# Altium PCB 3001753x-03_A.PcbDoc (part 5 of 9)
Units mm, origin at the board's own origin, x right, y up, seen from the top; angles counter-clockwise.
Board outline 210 x 130 mm, 8 copper layers (1-TOP, 2-GND, 3-INTOP, 4-PWR, 5-PWR, 6-INBOT, 7-GND, 8-BOTTOM), stack 1.646 mm thick; 676 components, 623 nets, 2861 pads, 2382 vias.
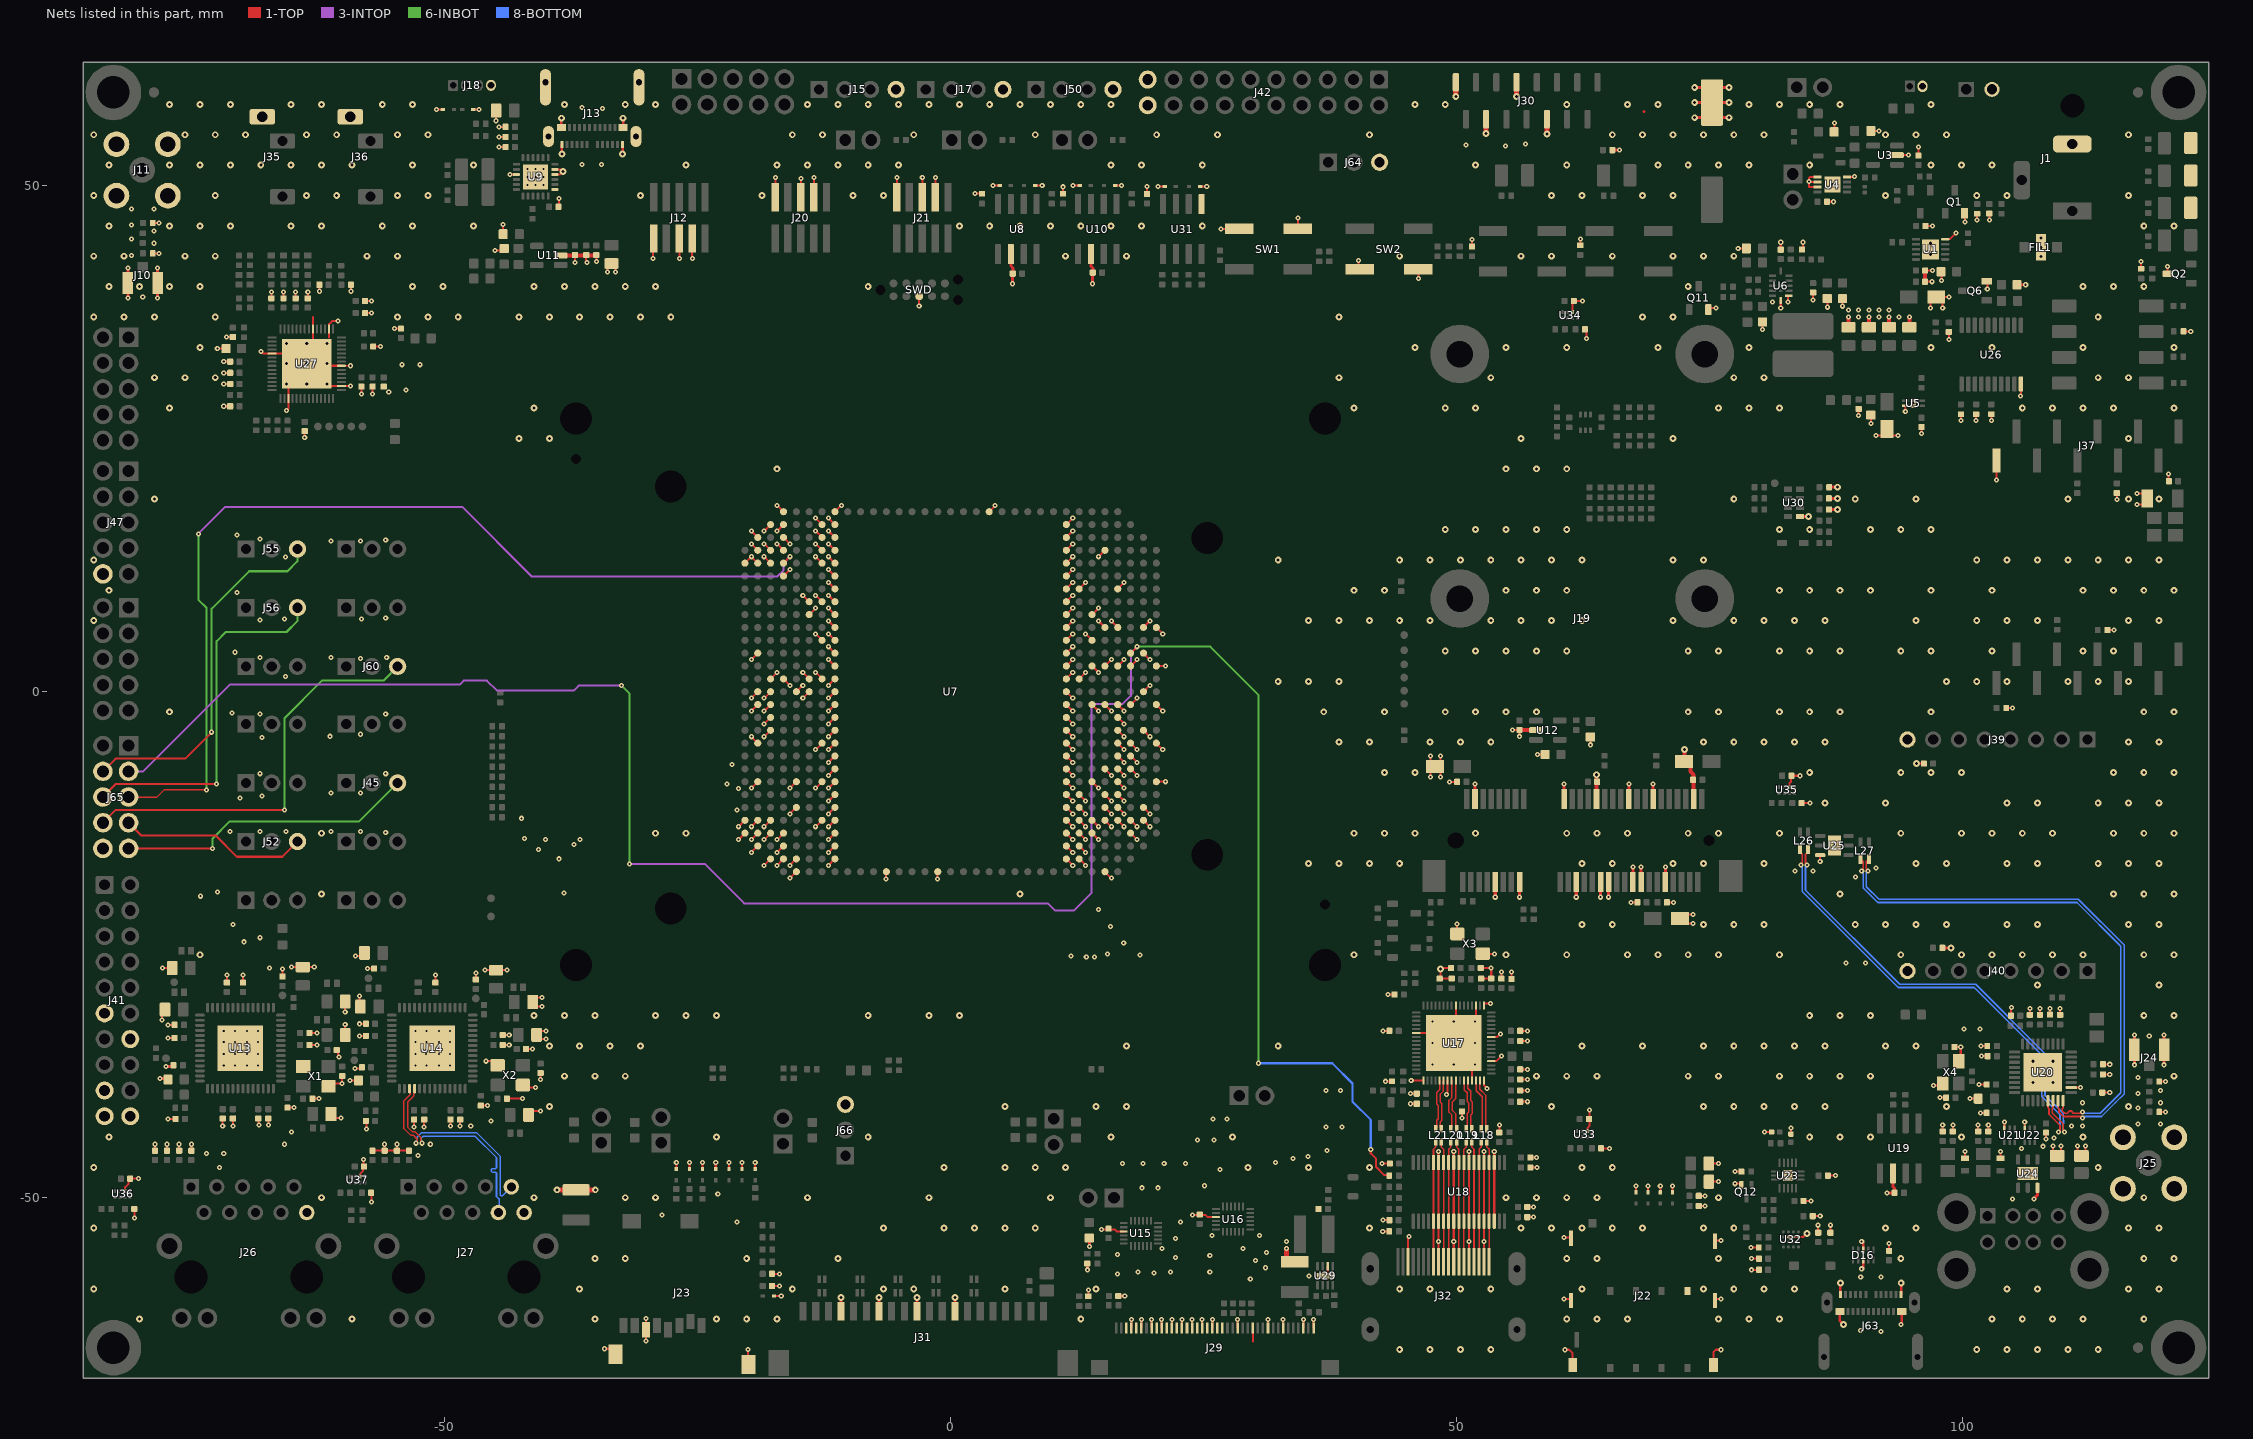
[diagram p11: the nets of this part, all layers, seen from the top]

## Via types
v1: diameter 0.5, hole 0.2, 1-TOP to 8-BOTTOM, 1547 vias
v2: diameter 0.68, hole 0.3, 1-TOP to 8-BOTTOM, 835 vias

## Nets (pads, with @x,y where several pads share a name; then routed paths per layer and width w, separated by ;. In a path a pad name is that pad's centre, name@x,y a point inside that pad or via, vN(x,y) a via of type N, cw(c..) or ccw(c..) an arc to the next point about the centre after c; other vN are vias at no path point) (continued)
ETH2_TXRXD_N: J27.9 U14.17 | length 21.8
  1-TOP w0.15: U14.17@-53.45,-39.2 -53.377,-39.273 -53.377,-39.777 -54,-40.4 -54,-43.147 -53.347,-43.8 -53.077,-43.8 -52.677,-44.2 -52.677,-44.477 v1(-52.8,-44.6)
  8-BOTTOM w0.15: v1(-52.8,-44.6) -52.677,-44.477 -52.677,-43.976 -52.247,-43.546 -46.829,-43.546 -44.504,-45.871 -44.504,-49.714 -44.416,-49.802 -44.292,-49.802 J27.9@-43.4,-48.91
ETH2_TXRXD_P: J27.8 U14.18 | length 21.7
  1-TOP w0.15: U14.18@-52.95,-39.2 -53.023,-39.273 -53.023,-39.924 -53.646,-40.547 -53.646,-43 -53.2,-43.446 -52.93,-43.446 -52.323,-44.053 -52.323,-44.477 v1(-52.2,-44.6)
  8-BOTTOM w0.15: v1(-52.2,-44.6) -52.323,-44.477 -52.323,-44.123 -52.1,-43.9 -46.976,-43.9 -44.858,-46.018 -44.858,-46.588 -44.858,-47.013 -44.946,-47.101 -45.294,-47.101 -45.364,-47.171 -45.364,-47.381 -45.294,-47.451 -44.946,-47.451 -44.858,-47.539 -44.858,-47.713 -44.858,-49.861 -44.581,-50.138 J27.8@-44.581,-51.361
FAA_N: L27.1 U20.8 | length 54.3
  1-TOP w0.168: v1(90.6,-17.7) 90.459,-17.559 90.459,-16.791 L27.1@90.7,-16.55 ; U20.8@109.4,-40.4 109.4,-41.1 109.491,-41.191 109.491,-41.541 109.775,-41.825 109.909,-41.959 111.659,-41.959 v1(111.8,-42.1)
  8-BOTTOM w0.168: v1(90.6,-17.7) 90.459,-17.841 90.459,-19.259 91.7,-20.5 111.4,-20.5 115.918,-25.018 115.918,-39.732 115.073,-40.576 113.691,-41.959 111.941,-41.959 v1(111.8,-42.1)
FAA_P: L27.4 U20.9 | length 53.5
  1-TOP w0.168: L27.4@89.9,-16.55 90.141,-16.791 90.141,-17.559 v1(90,-17.7) ; U20.9@109.9,-40.4 109.9,-41.1 109.809,-41.191 109.809,-41.409 110.041,-41.641 110.333,-41.641 110.432,-41.543 110.432,-41.483 110.505,-41.41 110.726,-41.41 110.8,-41.483 110.8,-41.543 110.898,-41.641 111.659,-41.641 v1(111.8,-41.5)
  8-BOTTOM w0.168: v1(90,-17.7) 90.141,-17.841 90.141,-19.391 91.568,-20.818 111.268,-20.818 115.6,-25.15 115.6,-39.6 113.559,-41.641 111.941,-41.641 v1(111.8,-41.5)
G_N: L26.4 U20.6 | length 46.5
  1-TOP w0.168: L26.4@83.892,-15.84 84.008,-15.956 84.035,-15.956 84.133,-16.054 84.133,-16.467 84.133,-16.959 v1(83.992,-17.1) ; U20.6@108.4,-40.4 108.4,-41.1 108.491,-41.191 108.491,-41.741 109.582,-42.832 109.582,-43.359 v1(109.441,-43.5)
  8-BOTTOM w0.168: v1(83.992,-17.1) 84.133,-17.241 84.133,-18.202 84.133,-18.333 84.133,-19.733 93.618,-29.218 101.118,-29.218 107.782,-35.882 107.782,-39.982 109.582,-41.782 109.582,-43.359 v1(109.441,-43.5)
G_P: L26.1 U20.7 | length 46.6
  1-TOP w0.168: v1(84.592,-17.1) 84.451,-16.959 84.451,-16.9 84.451,-16.054 84.55,-15.956 84.576,-15.956 L26.1@84.692,-15.84 ; U20.7@108.9,-40.4 108.9,-41.1 108.809,-41.191 108.809,-41.609 109.9,-42.7 109.9,-43.359 v1(110.041,-43.5)
  8-BOTTOM w0.168: v1(84.592,-17.1) 84.451,-17.241 84.451,-19.602 93.75,-28.9 101.25,-28.9 108.1,-35.75 108.1,-39.85 109.9,-41.65 109.9,-42.325 109.925,-42.35 109.925,-42.675 109.9,-42.7 109.9,-43.359 v1(110.041,-43.5)
GND: C1.1 C2.2 C3.1 C4.1 C5.1 C6.2 C7.1 C8.1 C9.2 C10.2 C12.1 C13.1 C14.1 C15.1 C16.2 C17.1 C18.1 C19.1 C20.1 C21.1 C22.1 C24.1 C25.1 C26.1 C27.1 C28.1 C29.2 C30.1 C31.2 C32.2 C33.1 C34.2 C35.1 C36.1 C37.1 C38.1 C39.2 C40.2 C41.2 C42.2 C43.1 C44.1 C45.1 C46.1 C47.1 C48.1 C49.1 C50.1 C51.1 C52.1 C53.1 C54.1 C55.1 C56.1 C57.1 C58.1 C59.1 C60.1 C61.1 C62.1 C63.1 C64.1 C65.1 C66.1 C67.2 C68.1 C69.1 C70.1 C71.1 C72.1 C73.1 C74.1 C75.1 C76.1 C77.1 C78.1 C79.1 C81.1 C82.1 C83.1 C84.1 C85.1 C86.1 C87.1 C88.1 C89.1 C90.1 C91.1 C92.1 C93.1 C94.2 C95.1 C96.1 C97.1 C98.1 C99.1 C100.1 C101.1 C102.1 C103.1 C104.1 C105.1 C106.1 C108.2 C109.2 C110.1 C111.1 C112.1 C113.1 C114.1 C115.1 C116.1 C118.1 C119.1 C120.1 C121.1 C122.1 C123.1 C124.1 C125.1 C126.1 C127.1 C128.1 C129.1 C130.1 C131.1 C132.1 C133.1 C134.1 C135.1 C136.1 C137.2 C138.2 C139.2 C140.1 C141.1 C142.1 C143.1 C144.1 C145.1 C146.2 C147.1 C148.1 C149.1 C150.1 C151.1 C152.1 C153.1 C154.1 C155.1 C156.1 C157.1 C158.2 C161.2 C164.2 C165.2 C166.2 C168.2 C170.2 C171.1 C173.1 C174.1 C175.1 C176.2 C177.2 C178.2 C179.1 C180.1 C181.1 C182.1 C183.2 C184.2 C185.1 C186.1 C187.1 C188.1 C189.1 C190.1 C191.1 C192.1 C193.1 C194.1 C195.1 C196.1 C197.1 C198.1 C199.1 C200.1 C201.1 C202.1 C203.2 C204.1 C205.2 C206.1 C207.2 C208.1 C209.2 C210.1 C211.2 D1.2 D3.1 D4.1 D7.1 D8.1 D9.1 D10.1 D11.1 D12.1 D13.1 D14.1 D16.3 D16.8 D19.1 D20.1 D22.A D23.A D24.2 D25.2 D26.2 D27.2 D28.2 D29.2 D30.2 D32.K D33.K D34.K FIL1.2 J1.2 J2.2 J4.2 J10.2 J10.3 J11.2 J11.3 J11.4 J11.5 J12.4 J12.6 J12.10 J13.A1 J13.A12 J13.B1 J13.B12 J13.MT1 J13.MT2 J13.MT3 J13.MT4 J15.4 J17.4 J18.4 J19.4 J19.9 J19.15 J19.18 J19.21 J19.26 J19.27 J19.29 J19.34 J19.35 J19.37 J19.40 J19.43 J19.50 J20.3 J20.5 J20.9 J21.3 J21.5 J21.9 J22.5 J22.11 J22.12 J22.13 J22.14 J22.15 J22.16 J23.6 J23.11 J23.12 J24.2 J24.3 J25.2 J25.3 J25.4 J25.5 J26.10 J27.10 J29.3 J29.4 J29.5 J29.6 J29.8 J29.9 J29.10 J29.11 J29.12 J29.13 J29.14 J29.15 J29.16 J29.17 J29.18 J29.19 J29.20 J29.21 J29.22 J29.25 J29.28 J29.31 J29.34 J29.38 J29.40 J30.6 J30.9 J30.12 J30.15 J31.4 J31.7 J31.10 J31.13 J32.2 J32.5 J32.8 J32.11 J32.17 J35.1 J36.1 J37.10 J39.8 J40.8 J41.11 J41.14 J41.17 J41.19 J41.20 J42.19 J42.20 J47.10 J50.4 J63.A1 J63.A12 J63.B1 J63.B12 J64.3 J65.10 J66.3 L24.1 L25.1 Q1.S Q2.D Q6.S Q11.S Q12.S R11.2 R14.2 R21.1 R31.1 R32.1 R59.1 R60.1 R67.1 R78.1 R79.1 R83.1 R95.1 R96.1 R100.1 R102.1 R106.1 R111.1 R114.1 R116.1 R117.2 R124.2 R125.1 R126.1 R144.2 R145.1 R146.1 R147.1 R148.1 R150.1 R157.1 R158.1 R159.1 R194.1 R198.1 R200.2 R202.1 R204.2 R208.1 R209.1 R218.2 R229.1 SW1.1 SW1.2 SW2.1 SW2.2 SWD.3 U1.5 U1.11 U3.2 U4.4 U4.5 U4.6 U4.7 U4.9 U5.2 U5.5 U6.1 U6.12 U7.A4 U7.A5 U7.A25 U7.AF2 U7.AF3 U7.AF4 U7.AF5 U7.AF6 U7.AF7 U7.AF8 U7.AF9 U7.AF10 U7.AF11 U7.AF12 U7.AF13 U7.AF14 U7.AF15 U7.AF16 U7.AF17 U7.AF18 U7.AF19 U7.AF20 U7.AF21 U7.AF22 U7.AF23 U7.AF24 U7.AF25 U7.AF26 U7.AF27 U7.AF28 U7.AG2 U7.AG3 U7.AG4 U7.AG5 U7.AG6 U7.AG7 U7.AG16 U7.AG23 U7.AH4 U7.AH5 U7.AH8 U7.AH14 U7.AH17 U7.AH19 U7.AH21 U7.AJ1 U7.AJ5 U7.AJ6 U7.AJ7 U7.AJ9 U7.AJ14 U7.AJ17 U7.AJ20 U7.AJ26 U7.AK5 U7.AK6 U7.AK7 U7.AK8 U7.AK9 U7.AK10 U7.AK11 U7.AK12 U7.AK13 U7.AK14 U7.AK17 U7.AK20 U7.AK23 U7.AL4 U7.AL5 U7.AL9 U7.AL10 U7.AL11 U7.AL14 U7.AL17 U7.AM5 U7.AM6 U7.AM12 U7.AM15 U7.AM18 U7.AM20 U7.AN8 U7.AN11 U7.AN14 U7.AN17 U7.AN20 U7.B3 U7.B4 U7.B5 U7.B8 U7.B11 U7.B14 U7.B15 U7.B18 U7.B25 U7.B26 U7.B27 U7.C2 U7.C4 U7.C5 U7.C12 U7.C13 U7.C14 U7.C15 U7.C16 U7.C25 U7.C26 U7.C28 U7.D2 U7.D3 U7.D4 U7.D16 U7.D24 U7.D26 U7.D27 U7.D28 U7.D29 U7.E1 U7.E2 U7.E6 U7.E8 U7.E15 U7.F15 U7.F16 U7.F21 U7.F22 U7.G5 U7.G8 U7.G11 U7.G16 U7.G19 U7.G22 U7.G25 U7.G26 U7.G27 U7.G28 U7.H2 U7.H3 U7.H4 U7.H5 U7.H6 U7.H7 U7.H8 U7.H9 U7.H10 U7.H11 U7.H12 U7.H13 U7.H14 U7.H15 U7.H16 U7.H17 U7.H18 U7.H19 U7.H20 U7.H21 U7.H22 U7.H23 U7.H24 U7.H25 U7.H26 U7.H27 U7.H28 U7.H29 U7.M1 U7.T1 U7.Y29 U8.2 U9.3 U9.13 U9.16 U9.17 U9.25 U10.2 U11.2 U12.2 U13.57 U14.57 U15.9 U16.9 U17.6 U17.17 U17.23 U17.29 U17.32 U17.36 U17.42 U17.49 U17.51 U17.56 U17.65 U18.3 U18.5 U18.8 U18.11 U18.14 U18.25 U18.28 U18.31 U18.34 U18.36 U19.6 U20.11 U20.37 U21.3 U22.3 U23.17 U24.3 U24.7 U25.3 U25.7 U26.10 U27.3 U27.16 U27.21 U27.30 U27.34 U27.47 U27.57 U29.2 U29.9 U30.5 U31.5 U32.B3 U32.C3 U32.D3 U33.2 U34.2 U35.2 U36.2 U37.2 X1.2 X1.4 X2.2 X2.4 X3.2 X3.4 X4.2 X4.4 | length 613.4
  1-TOP w0.15: U27.16@-60.17,30.2 v1(-59.3,30.2) ; U27.21@-60.17,32.2 v1(-59.3,32.2)
  1-TOP w0.168: U21.3@104.1,-43.15 v1(104.1,-42.5) ; U22.3@106.1,-43.15 v1(106.1,-42.5)
  1-TOP w0.2: U36.2@-81.55,-49.3 -81.549,-49.299 -81.549,-48.949 -81.2,-48.6 C208.1@-81.2,-48.3 ; C208.1@-81.04,-48.1 v1(-80.2,-48.1) ; C209.2@-80.64,-51.1 -80.6,-51.14 v1(-80.6,-52) ; R59.1@-78.82,43.3 v1(-78.2,43.3) ; R60.1@-78.82,46.3 v1(-78.2,46.3) ; C57.1@-78.6,-45.34 v1(-78.6,-44.7) ; v1(-77.9,-32.44) C76.1@-77.9,-31.8 ; v1(-77.84,-27.3) C66.1@-77.2,-27.3 ; C56.1@-77.4,-45.34 v1(-77.4,-44.7) ; v1(-77.3,-42.2) C67.2@-76.56,-42.2 ; v1(-77.3,-34.2) C77.1@-76.66,-34.2 ; v1(-77.3,-32.9) C72.1@-76.66,-32.9 ; C55.1@-76.2,-45.34 v1(-76.2,-44.7) ; C54.1@-75,-45.34 v1(-75,-44.7) ; v1(-72.44,33.9) C180.1@-71.8,33.9 ; v1(-71.9,-42.9) C73.1@-71.9,-42.26 ; v1(-71.8,28.2) C173.1@-71.16,28.2 ; v1(-71.8,30.4) C178.2@-71.16,30.4 ; v1(-71.8,31.5) C177.2@-71.16,31.5 ; v1(-71.8,32.6) C181.1@-71.16,32.6 ; v1(-71.54,35.04) C158.2@-70.9,35.04 ; C65.1@-71.5,-28.74 v1(-71.5,-28) ; U13.57@-71.4,-36.45 U13.57@-70.15,-35.2 ; v1(-70.9,-42.9) C61.1@-70.9,-42.26 ; C64.1@-69.9,-28.74 v1(-69.9,-28) ; C60.1@-68.4,-42.26 -68.35,-42.31 -68.35,-42.75 v1(-68.3,-42.8) ; v1(-68.1,33.6) -67.9,33.4 U27.47@-67.03,33.4 -66.1,33.4 ; v1(-67.4,-42.8) C74.1@-67.4,-42.26 ; C161.2@-67.1,38.86 v1(-67.1,39.5) ; C78.1@-66,-28.14 v1(-66,-27.4) ; C165.2@-65.9,38.86 v1(-65.9,39.5) ; v1(-65.6,27.8) -65.4,28 U27.3@-65.4,28.97 -65.4,29.9 ; R106.1@-65.5,-41.08 v1(-64.86,-41.08) ; v1(-65.1,-27.2) -64.3,-27.2 C79.1@-64,-26.9 ; C166.2@-64.7,38.86 v1(-64.7,39.5) ; v1(-63.8,25.1) C171.1@-63.8,25.74 ; C79.1@-63.6,-27.2 v1(-62.86,-27.2) ; v2(-63.6,32.4) -61.4,30.2 U27.16@-60.17,30.2 ; C170.2@-63.5,38.86 v1(-63.5,39.5) ; C58.1@-63.34,-34.9 v1(-62.6,-34.9) ; C75.1@-63.34,-33.7 v1(-62.6,-33.7) ; C71.1@-63.04,-40.2 v1(-62.4,-40.2) ; -63,34.9 U27.34@-63,35.83 -63,37 ; v1(-62.36,39.56) C164.2@-62.36,40.2 ; X1.4@-61.45,-38.975 -61.175,-38.7 v1(-60.1,-38.7) C68.1@-60.1,-37.96 ; -61.4,35 U27.30@-61.4,35.83 -61.4,36.3 -61.1,36.6 v1(-60.5,36.6) ; C62.1@-61.2,-41.7 -61.2,-42.1 v1(-60.2,-42.1) ; -61.1,32.2 U27.21@-60.17,32.2 ; C69.1@-60.64,-35.4 -60.5,-35.54 -60.5,-36 v1(-60.4,-36.1) ; C70.1@-59.8,-33.5 v1(-59.8,-32.86) ; v1(-59.8,-31.64) C59.1@-59.8,-31 ; v1(-59.34,-38.4) R111.1@-58.7,-38.4 ; v1(-59.24,39.56) C168.2@-59.24,40.2 ; v1(-58.84,-37.2) C90.1@-58.2,-37.2 ; v1(-58.8,-26.1) -58.2,-26.1 C93.1@-57.9,-25.8 ; v1(-58.4,-34) C104.1@-57.76,-34 C104.1@-57.56,-34 ; v1(-58.4,-32.8) C99.1@-57.76,-32.8 C99.1@-57.56,-32.8 ; C103.1@-58.4,-30.7 v1(-58.4,-30.06) ; U37.2@-58.35,-47.9 -58.3,-47.85 -58.3,-47.6 -58.061,-47.361 -58.061,-46.901 -58,-46.84 v1(-58,-46.2) ; v1(-58.2,29.4) C184.2@-58.2,30.14 ; C179.1@-57.84,37.4 v1(-57.2,37.4) ; C174.1@-57.84,38.6 v1(-57.2,38.6) ; C94.2@-57.76,-42.4 -57.7,-42.46 v1(-57.7,-43.2) ; v1(-57.59,-27.35) C91.1@-56.95,-27.35 ; C211.2@-57.24,-49.5 -57.2,-49.54 v1(-57.2,-50.4) ; C84.1@-57.1,-45.34 C83.1@-55.9,-45.34 ; v1(-57.1,29.4) C183.2@-57.1,30.14 ; C176.2@-57.04,34.1 v1(-56.3,34.1) ; v1(-55.9,-44.7) C83.1@-55.9,-45.34 ; v1(-55.5,29.6) v1@-55.5,29.64 ; v1(-54.94,35.86) C175.1@-54.3,35.86 ; v1(-54.7,-44.7) C82.1@-54.7,-45.34 ; C81.1@-53.5,-45.34 C82.1@-54.7,-45.34 ; v1(-53,-43) C100.1@-53,-42.26 ; U14.57@-52.45,-36.45 v1(-51.8,-35.8) U14.57@-51.2,-35.2 ; v1(-52,-43) C88.1@-52,-42.26 ; C92.1@-50.9,-28.74 v1(-50.9,-28) ; v1(-50.79,57.5) D10.1@-50.15,57.5 ; v1(-49.4,-42.9) C87.1@-49.4,-42.26 ; v1(-48.45,-42.9) C101.1@-48.45,-42.26 ; D9.1@-47.25,57.5 v1(-46.6,57.5) ; C105.1@-46.9,-28.44 v1(-46.9,-27.8) ; R114.1@-46.4,-40.88 v1(-45.76,-40.88) ; v1(-46,-27.5) -45.1,-27.5 C106.1@-44.9,-27.3 ; v1(-45.9,-36.5) -45.15,-36.5 X2.2@-44.75,-36.9 ; v1(-45,43.6) -44.27,43.6 C33.1@-44.1,43.77 ; v1(-44.9,56.4) C35.1@-44.9,56.9 ; v1(-44.6,53.8) C30.1@-43.96,53.8 ; v1(-44.6,54.8) -44.06,54.8 C37.1@-43.96,54.9 ; v1(-44.6,55.8) C36.1@-43.96,55.8 ; C106.1@-44.4,-27.5 v1(-43.8,-27.5) ; C85.1@-44.24,-34.9 v1(-43.6,-34.9) ; C102.1@-44.24,-33.9 v1(-43.6,-33.9) ; R79.1@-44.2,45.5 v1(-44.2,46.14) ; C98.1@-43.84,-40.2 v1(-42.3,-40.2) ; v1(-43.54,51.1) U9.3@-42.9,51.1 ; X2.4@-42.3,-39.1 v1(-41,-39.1) ; C96.1@-41.94,-35.3 v1(-41.3,-35.3) ; C89.1@-41.7,-41.8 -41.3,-41.4 v1(-40.5,-41.4) ; C86.1@-41.1,-31.1 v1(-40.36,-31.1) ; C86.1@-41.1,-30.2 v1(-40.36,-30.2) ; C97.1@-40.7,-34.3 v1(-39.96,-34.3) ; C97.1@-40.7,-33.5 v1(-39.96,-33.5) ; v1(-40.5,-38.3) C95.1@-40.5,-37.66 ; U9.16@-39.1,51.1 -38.6,51.1 v2(-38.3,51.4) -38.5,51.6 U9.17@-39.1,51.6 ; C31.2@-38.74,47.9 -38.7,47.94 v1(-38.7,48.7) ; v1(-37.1,42.4) -37.1,43.1 C34.2@-37.1,43.14 ; C27.1@-36,43.14 -36,43.1 -36,42.5 v1(-35.9,42.4) ; C28.1@-35.04,43.1 C28.1@-35,43.14 v1(-35,42.5) ; v1(-34.2,-64.9) -33.65,-64.9 J23.11@-33.1,-65.45 ; v1(-33.9,41.46) C26.1@-33.9,42.1 ; v1(-33.1,41.46) C26.1@-33.1,42.1 ; v1(-30.1,-64.125) J23.6@-30.1,-63.025 v1(-30.1,-61.925) ; v1(-29.4,42.8) -29.4,44.708 J12.10@-29.34,44.768 ; D28.2@-27.1,-47.15 v1(-27.1,-46.5) ; v1(-26.8,42.8) J12.6@-26.8,43.768 ; D24.2@-25.8,-47.15 v1(-25.8,-46.5) ; J12.4@-25.53,43.768 -25.53,42.83 v1(-25.5,42.8) ; D25.2@-24.5,-47.15 v1(-24.5,-46.5) ; D27.2@-23.2,-47.15 v1(-23.2,-46.5) ; D29.2@-21.9,-47.15 v1(-21.9,-46.5) ; v1(-20.955,-14.605) U7.A4@-20.32,-13.97 ; v1(-20.955,-13.335) U7.A5@-20.32,-12.7 ; D26.2@-20.6,-47.15 v1(-20.6,-46.5) ; U7.A25@-20.32,12.7 v1(-19.685,13.335) U7.B25@-19.05,12.7 ; J23.12@-20,-65.7 v1(-20,-64.96) ; v1(-19.685,-15.875) U7.B3@-19.05,-15.24 ; v1(-19.685,-14.605) U7.B4@-19.05,-13.97 ; v1(-19.685,-13.335) U7.B5@-19.05,-12.7 ; v1(-19.685,-9.525) U7.B8@-19.05,-8.89 ; v1(-19.685,-4.445) U7.B11@-19.05,-5.08 ; v1(-19.685,-1.905) U7.B14@-19.05,-1.27 ; v1(-19.685,-0.635) U7.B15@-19.05,0 ; v1(-19.685,3.175) U7.B18@-19.05,3.81 ; v1(-19.685,14.605) U7.B26@-19.05,13.97 ; v1(-19.685,15.875) U7.B27@-19.05,15.24 ; D30.2@-19.3,-47.15 v1(-19.3,-46.5) ; v1(-18.415,-17.145) U7.C2@-17.78,-16.51 ; v1(-18.415,-14.605) U7.C4@-17.78,-13.97 ; v1(-18.415,-13.335) U7.C5@-17.78,-12.7 ; v1(-18.415,-4.445) U7.C12@-17.78,-3.81 ; v1(-18.415,-3.175) U7.C13@-17.78,-2.54 ; v1(-18.415,-1.905) U7.C14@-17.78,-1.27 ; v1(-18.415,-0.635) U7.C15@-17.78,0 ; v1(-18.415,13.335) U7.C25@-17.78,12.7 ; v1(-18.415,14.605) U7.C26@-17.78,13.97 ; v1(-18.415,15.875) U7.C28@-17.78,16.51 ; U7.C16@-17.78,1.27 v1(-17.145,1.905) ; C48.1@-17.64,-58.7 v1(-16.92,-58.7) ; C49.1@-17.64,-57.5 v1(-16.92,-57.5) ; D1.2@-17.45,-59.7 v1(-16.73,-59.7) ; J20.9@-17.34,48.832 -17.3,48.872 v1(-17.3,50.8) ; v1(-17.145,-17.145) U7.D2@-16.51,-16.51 ; v1(-17.145,-15.875) U7.D3@-16.51,-15.24 ; v1(-17.145,-14.605) U7.D4@-16.51,-13.97 ; v1(-17.145,14.605) U7.D26@-16.51,13.97 ; v1(-17.145,15.875) U7.D28@-16.51,16.51 ; v1(-17.145,18.415) U7.D29@-16.51,17.78 ; U7.D16@-16.51,1.27 v1(-15.875,0.635) ; U7.D24@-16.51,11.43 v1(-15.875,12.065) ; U7.D27@-16.51,15.24 v1(-15.875,14.605) ; v1(-15.875,-18.415) U7.E1@-15.24,-17.78 ; v1(-15.875,-17.145) U7.E2@-15.24,-16.51 ; v1(-15.875,-12.065) U7.E6@-15.24,-11.43 ; v1(-15.875,-9.525) U7.E8@-15.24,-8.89 ; U7.E15@-15.24,0 v1(-14.605,0.635) ; J20.5@-14.8,47.796 J20.5@-14.8,48.832 v1(-14.8,50.7) ; v1(-14.605,-0.635) U7.F15@-13.97,0 ; v1(-14.605,1.905) U7.F16@-13.97,1.27 ; v1(-14.605,9.525) U7.F22@-13.97,8.89 ; U7.F21@-13.97,7.62 v1(-13.335,8.255) ; J20.3@-13.53,48.832 -13.5,48.862 v1(-13.5,50.8) ; v1(-13.335,-13.335) U7.G5@-12.7,-12.7 ; v1(-13.335,-9.525) U7.G8@-12.7,-8.89 ; v1(-13.335,-5.715) U7.G11@-12.7,-5.08 ; v1(-13.335,1.905) U7.G16@-12.7,1.27 ; v1(-13.335,5.715) U7.G19@-12.7,5.08 ; v1(-13.335,9.525) U7.G22@-12.7,8.89 ; v1(-13.335,13.335) U7.G25@-12.7,12.7 ; v1(-13.335,14.605) U7.G26@-12.7,13.97 ; v1(-13.335,15.875) U7.G27@-12.7,15.24 ; v1(-13.335,17.145) U7.G28@-12.7,16.51 ; v1(-12.065,-17.145) U7.H2@-11.43,-16.51 ; v1(-12.065,-15.875) U7.H3@-11.43,-15.24 ; v1(-12.065,-14.605) U7.H4@-11.43,-13.97 ; v1(-12.065,-13.335) U7.H5@-11.43,-12.7 ; v1(-12.065,-12.065) U7.H6@-11.43,-11.43 ; v1(-12.065,-10.795) U7.H7@-11.43,-10.16 ; v1(-12.065,-9.525) U7.H8@-11.43,-8.89 ; v1(-12.065,-8.255) U7.H9@-11.43,-7.62 ; v1(-12.065,-6.985) U7.H10@-11.43,-6.35 ; v1(-12.065,-5.715) U7.H11@-11.43,-5.08 ; v1(-12.065,-4.445) U7.H12@-11.43,-3.81 ; v1(-12.065,-3.175) U7.H13@-11.43,-2.54 ; v1(-12.065,-1.905) U7.H14@-11.43,-1.27 ; v1(-12.065,-0.635) U7.H15@-11.43,0 ; v1(-12.065,0.635) U7.H16@-11.43,1.27 ; v1(-12.065,3.175) U7.H17@-11.43,2.54 ; v1(-12.065,4.445) U7.H18@-11.43,3.81 ; v1(-12.065,5.715) U7.H19@-11.43,5.08 ; v1(-12.065,6.985) U7.H20@-11.43,6.35 ; v1(-12.065,8.255) U7.H21@-11.43,7.62 ; v1(-12.065,9.525) U7.H22@-11.43,8.89 ; v1(-12.065,10.795) U7.H23@-11.43,10.16 ; v1(-12.065,12.065) U7.H24@-11.43,11.43 ; v1(-12.065,13.335) U7.H25@-11.43,12.7 ; v1(-12.065,14.605) U7.H26@-11.43,13.97 ; v1(-12.065,15.875) U7.H27@-11.43,15.24 ; v1(-12.065,17.145) U7.H28@-11.43,16.51 ; U7.H29@-11.43,17.78 v1(-10.795,18.415) ; v1(-6.4,-18.5) -6.4,-17.83 U7.M1@-6.35,-17.78 ; J21.9@-5.34,48.832 -5.3,48.872 v1(-5.3,50.8) ; v1(-3.1,38.1) SWD.3@-3.1,39.065 ; J21.5@-2.8,47.832 J21.5@-2.8,48.832 v1(-2.8,50.8) ; J21.3@-1.53,48.832 -1.5,48.862 v1(-1.5,50.8) ; v1(-1.3,-18.5) -1.3,-17.81 U7.T1@-1.27,-17.78 ; v1(2.4,49.2) R67.1@3.1,49.2 ; U7.Y29@3.81,17.78 4.4,18.37 v1(4.4,18.4) ; v1(4.2,50) D4.1@4.9,50 ; D3.1@8.35,50 v1(9.05,50) ; R78.1@11.1,49.18 v1(11.1,49.88) ; U7.AF2@11.43,-16.51 v1(12.065,-17.145) ; U7.AF3@11.43,-15.24 v1(12.065,-15.875) ; U7.AF4@11.43,-13.97 v1(12.065,-14.605) ; U7.AF5@11.43,-12.7 v1(12.065,-13.335) ; U7.AF6@11.43,-11.43 v1(12.065,-12.065) ; U7.AF7@11.43,-10.16 v1(12.065,-10.795) ; U7.AF8@11.43,-8.89 v1(12.065,-9.525) ; U7.AF9@11.43,-7.62 v1(12.065,-8.255) ; U7.AF10@11.43,-6.35 v1(12.065,-6.985) ; U7.AF11@11.43,-5.08 v1(12.065,-5.715) ; U7.AF12@11.43,-3.81 v1(12.065,-4.445) ; U7.AF13@11.43,-2.54 v1(12.065,-3.175) ; U7.AF14@11.43,-1.27 v1(12.065,-1.905) ; U7.AF15@11.43,0 v1(12.065,-0.635) ; U7.AF16@11.43,1.27 v1(12.065,1.905) ; U7.AF17@11.43,2.54 v1(12.065,3.175) ; U7.AF18@11.43,3.81 v1(12.065,4.445) ; U7.AF19@11.43,5.08 v1(12.065,5.715) ; U7.AF20@11.43,6.35 v1(12.065,6.985) ; U7.AF21@11.43,7.62 v1(12.065,8.255) ; U7.AF22@11.43,8.89 v1(12.065,9.525) ; U7.AF23@11.43,10.16 v1(12.065,10.795) ; U7.AF24@11.43,11.43 v1(12.065,12.065) ; U7.AF25@11.43,12.7 v1(12.065,13.335) ; U7.AF26@11.43,13.97 v1(12.065,14.605) ; U7.AF27@11.43,15.24 v1(12.065,15.875) ; U7.AF28@11.43,16.51 v1(12.065,17.145) ; v1(12.1,50) D8.1@12.786,50 ; U7.AG2@12.7,-16.51 v1(13.335,-17.145) ; U7.AG3@12.7,-15.24 v1(13.335,-15.875) ; U7.AG4@12.7,-13.97 v1(13.335,-14.605) ; U7.AG5@12.7,-12.7 v1(13.335,-13.335) ; U7.AG6@12.7,-11.43 v1(13.335,-12.065) ; U7.AG7@12.7,-10.16 v1(13.335,-10.795) ; U7.AG16@12.7,1.27 v1(13.335,1.905) ; U7.AG23@12.7,10.16 v1(13.335,10.795) ; v1(13.335,5.715) U7.AH19@13.97,5.08 ; R218.2@13.6,-59.72 v1(13.6,-59.1) ; U7.AH4@13.97,-13.97 v1(14.605,-14.605) ; U7.AH5@13.97,-12.7 v1(14.605,-13.335) ; U7.AH8@13.97,-8.89 v1(14.605,-9.525) ; U7.AH14@13.97,-1.27 v1(14.605,-1.905) ; U7.AH17@13.97,2.54 v1(14.605,1.905) ; U7.AH21@13.97,7.62 v1(14.605,8.255) ; v1(14.605,6.985) U7.AJ20@15.24,6.35 ; v1(14.605,13.335) U7.AJ26@15.24,13.97 ; v1(14.9,-53.1) 16.2,-53.1 16.4,-53.3 U15.9@17.105,-53.3 ; U7.AJ1@15.24,-17.78 v1(15.875,-18.415) ; U7.AJ5@15.24,-12.7 v1(15.875,-13.335) ; U7.AJ6@15.24,-11.43 v1(15.875,-12.065) ; U7.AJ7@15.24,-10.16 v1(15.875,-10.795) ; U7.AJ9@15.24,-7.62 v1(15.875,-8.255) ; U7.AJ14@15.24,-1.27 v1(15.875,-1.905) ; U7.AJ17@15.24,2.54 v1(15.875,3.175) ; v1(15.875,6.985) U7.AK20@16.51,6.35 ; D7.1@16.173,50 v1(16.9,50) ; U7.AK5@16.51,-12.7 v1(17.145,-13.335) ; U7.AK6@16.51,-11.43 v1(17.145,-12.065) ; U7.AK7@16.51,-10.16 v1(17.145,-10.795) ; U7.AK8@16.51,-8.89 v1(17.145,-9.525) ; U7.AK9@16.51,-7.62 v1(17.145,-8.255) ; U7.AK10@16.51,-6.35 v1(17.145,-6.985) ; U7.AK11@16.51,-5.08 v1(17.145,-5.715) ; U7.AK12@16.51,-3.81 v1(17.145,-4.445) ; U7.AK13@16.51,-2.54 v1(17.145,-3.175) ; U7.AK14@16.51,-1.27 v1(17.145,-1.905) ; U7.AK17@16.51,2.54 v1(17.145,3.175) ; U7.AK23@16.51,10.16 v1(17.145,10.795) ; U7.AL4@17.78,-13.97 v1(18.415,-14.605) ; U7.AL5@17.78,-12.7 v1(18.415,-13.335) ; U7.AL9@17.78,-7.62 v1(18.415,-8.255) ; U7.AL10@17.78,-6.35 v1(18.415,-6.985) ; U7.AL11@17.78,-5.08 v1(18.415,-5.715) ; U7.AL14@17.78,-1.27 v1(18.415,-0.635) ; U7.AL17@17.78,2.54 v1(18.415,3.175) ; J29.4@17.85,-62.85 v1(17.85,-62) ; J29.6@18.85,-62.85 v1(18.85,-62) ; U7.AM5@19.05,-12.7 v1(19.685,-13.335) ; U7.AM6@19.05,-11.43 v1(19.685,-12.065) ; U7.AM12@19.05,-3.81 v1(19.685,-4.445) ; U7.AM15@19.05,0 v1(19.685,0.635) ; U7.AM18@19.05,3.81 v1(19.685,3.175) ; U7.AM20@19.05,6.35 v1(19.685,6.985) ; C194.1@19.4,49.16 v1(19.4,49.9) ; J29.8@19.85,-62.85 v1(19.85,-62) ; U7.AN8@20.32,-8.89 v1(21.218,-8.89) ; U7.AN11@20.32,-5.08 v1(20.955,-5.715) ; U7.AN14@20.32,-1.27 v1(20.955,-1.905) ; U7.AN17@20.32,2.54 v1(21.218,2.54) ; U7.AN20@20.32,6.35 v1(20.955,5.715) ; v1(20.5,49.9) D20.1@21.05,49.9 ; J29.10@20.85,-62.85 v1(20.85,-62) ; J29.12@21.85,-62.85 v1(21.85,-62) ; J29.14@22.85,-62.85 v1(22.85,-62) ; J29.16@23.85,-62.85 v1(23.85,-62) ; v1(23.9,-51.7) 24.54,-51.7 C109.2@24.6,-51.64 24.66,-51.7 25.2,-51.7 25.4,-51.9 U16.9@26.205,-51.9 ; D19.1@24.75,49.9 v1(25.3,49.9) ; J29.18@24.85,-62.85 v1(24.85,-62) ; J29.20@25.85,-62.85 v1(25.85,-62) ; v1(26.7,45.7) SW1.1@27.4,45.7 ; J29.25@28.35,-62.85 v1(28.35,-62) ; 29.85,-64.2 J29.28@29.85,-62.85 ; J29.31@31.35,-62.85 v1(31.35,-62) ; J29.34@32.85,-62.85 v1(32.85,-62) ; C190.1@33.2,-56.3 C190.1@34,-56.3 ; SW1.2@33.2,45.7 SW1.2@33.7,45.7 ; SW1.2@34.3,45.727 34.427,45.6 34.7,45.6 34.3,46 v1(34.3,46.8) ; J29.38@34.85,-62.85 v1(34.85,-62) ; J29.40@35.85,-62.85 v1(35.85,-62) ; U29.9@37.2,-57.7 37.25,-57.65 U29.2@37.25,-56.765 ; SW2.2@40.3,41.9 v1(40.3,42.6) ; v1(42.6,-46.6) C115.1@43.34,-46.6 ; v1(42.685,-53.3) R126.1@43.32,-53.3 ; v1(42.7,-33.5) C126.1@43.345,-33.5 ; v1(42.705,-52.2) C119.1@43.34,-52.2 ; v1(42.97,-38.48) R124.2@43.605,-38.48 ; v1(43.2,-29.9) C125.1@43.845,-29.9 ; J32.17@45.2,-56.3 v1@45.2,-53.8 ; v1(45.41,-40.7) C120.1@46.045,-40.7 ; v1(45.41,-39.7) C121.1@46.045,-39.7 ; v1(45.5,-38.4) 45.505,-38.405 U17.17@46.7,-38.405 ; U17.6@45.995,-33.7 48.7,-33.7 v1(49.7,-34.7) 49.9,-34.5 U17.56@49.9,-30.995 ; v1(46.2,40.8) SW2.1@46.2,41.709 ; v1(47.4,-8.43) C40.2@47.4,-7.6 ; C40.2@47.4,-7.2 v1(47.4,-6.37) ; J32.11@48.2,-56.3 v1(48.2,-54.3) U18.25@48.2,-52.3 U18.14@48.2,-46.5 v1(48.2,-45.4) ; C123.1@48.305,-28.34 C123.1@48.325,-28.32 ; v1(48.4,-8.43) C40.2@48.4,-7.6 ; C40.2@48.4,-7.2 v1(48.4,-6.37) ; v1(49,-39.8) 49.1,-39.7 U17.23@49.1,-38.405 ; v1(49.3,-8.9) C44.1@50.04,-8.9 ; C116.1@49.445,-27.3 48.5,-27.3 v2(48.4,-27.4) 48.4,-28.245 C123.1@48.325,-28.32 ; R125.1@49.505,-28.32 C123.1@48.325,-28.32 ; J32.8@49.7,-56.3 v1(49.7,-54.3) U18.11@49.7,-46.5 v1(49.7,-45.4) ; X3.2@50,-23.6 v1(50,-22.965) ; v1(50.505,-42.095) C128.1@50.505,-41.46 ; J32.5@51.2,-56.3 v1(51.2,-54.3) U18.8@51.2,-46.5 v1(51.2,-45.4) ; U17.29@51.5,-38.405 51.5,-37.5 ; R209.1@51.5,43.98 v1(51.5,44.68) ; U17.65@51.9,-32.3 U17.51@51.9,-30.995 ; C114.1@52.365,-27.3 v1(53.4,-27.3) 53.405,-27.305 C135.1@53.405,-28.34 C136.1@52.405,-28.34 ; J32.2@52.7,-56.3 v1(52.7,-54.3) U18.5@52.7,-46.5 v1(52.7,-45.4) ; U17.32@52.7,-38.405 52.7,-38.9 v1(53,-39.2) ; U17.49@52.7,-30.8 v1(53.335,-30.8) ; X3.4@53.1,-25.9 v1(53.735,-25.9) ; U17.36@53.405,-36.5 53.9,-36.5 v1(54.4,-36) ; U17.42@53.405,-34.1 54,-34.1 v1(54.3,-33.8) ; U18.36@53.7,-52.3 U18.3@53.7,-46.5 v1(53.7,-45.4) ; C113.1@54.2,-43.54 v1(54.2,-42.8) ; C134.1@54.405,-28.34 v1(54.405,-27.705) ; v1(55.4,-27.7) 55.405,-27.705 C133.1@55.405,-28.38 ; v1(55.5,-3.8) 55.52,-3.78 C39.2@56.2,-3.78 ; v1(56.2,-4.4) C39.2@56.2,-3.78 ; C39.2@56.24,-3.8 C39.2@56.22,-3.78 ; C122.1@56.265,-40.5 v1(56.985,-40.5) ; C127.1@56.265,-39.4 v1(56.985,-39.4) ; C129.1@56.265,-38.3 v1(56.985,-38.3) ; C130.1@56.265,-37.3 v1(56.985,-37.3) ; C131.1@56.265,-34.5 v1(57,-34.5) ; C132.1@56.265,-33.5 56.9,-33.5 v1(57,-33.5) ; C124.1@56.96,-51.9 v1(57.595,-51.9) ; C118.1@56.96,-50.9 v1(57.595,-50.9) ; C111.1@57.26,-46 v1(57.895,-46) ; C112.1@57.266,-46.98 v1(57.901,-46.98) ; v1(57.99,-6.2) R83.1@58.73,-6.2 ; v1(60.6,-60) 61.27,-60 J22.15@61.29,-60.02 ; v1(60.6,-53.9) 61.25,-53.9 J22.14@61.29,-53.86 ; v1(60.7,-65) 61.1,-65 61.45,-65.35 J22.16@61.45,-66.37 ; U34.2@61.45,37.5 61.45,38.49 C204.1@61.56,38.6 v1(62.4,38.6) ; R208.1@62.2,44.1 v1(62.2,44.7) ; C205.2@62.66,35.8 62.8,35.66 v1(62.8,34.9) ; U33.2@62.893,-43.393 62.926,-43.36 62.926,-43.074 63.1,-42.9 63.1,-42.24 C202.1@63.06,-42.2 63.1,-42.16 v1(63.1,-41.3) ; v1(63.2,-5.24) C38.1@63.2,-4.6 ; C203.2@64.26,-45.1 v1(65.1,-45.1) ; v1(67.2,-20.8) C46.1@67.84,-20.8 ; D14.1@67.7,-49.45 v1(67.7,-48.815) ; D13.1@68.9,-49.45 v1(68.9,-48.815) ; D11.1@70.1,-49.45 v1(70.1,-48.815) ; C43.1@70.76,-20.8 v1(71.4,-20.8) ; D12.1@71.3,-49.45 v1(71.3,-48.815) ; C42.2@72.7,-22.9 v1(73.335,-22.9) ; C42.2@72.7,-22 v1(73.335,-22) ; C53.1@73.9,-50.8 v1(74.535,-50.8) ; C52.1@73.9,-49.8 v1(74.535,-49.8) ; Q11.S@74.85,37.75 75,37.9 v1(75.6,37.9) ; C51.1@75.2,-48.4 v1(75.835,-48.4) ; C50.1@75.2,-46.6 v1(75.835,-46.6) ; J22.11@75.35,-66.37 75.35,-65.25 75.6,-65 v1(76.1,-65) ; J22.12@75.51,-60 v1(76.1,-60) ; J22.13@75.51,-54.16 75.55,-54.2 76.015,-54.2 76.029,-54.186 76.043,-54.2 v1(76.1,-54.2) ; v1(77.5,-48.6) 77.99,-48.6 Q12.S@78.1,-48.71 ; v1(77.5,-47.4) R202.1@78.12,-47.4 ; v1(77.8,43.8) R32.1@78.6,43.8 ; v1(79.08,-54.9) R150.1@79.82,-54.9 ; v1(79.1,-57.1) C198.1@79.84,-57.1 ; v1(79.1,-56) C197.1@79.84,-56 ; v1(80.2,35.78) C24.1@80.2,36.4 ; v1(80.4,-43.5) C196.1@81.1,-43.5 ; v1(82,37.9) 82,38 U6.12@82,38.65 ; C25.1@82,43.66 v1(82,44.4) ; v1(82.7,38.5) 82.7,39 U6.1@82.8,39.1 ; U32.B3@82.75,-53.85 U32.C3@83.25,-53.85 U32.D3@83.75,-53.85 84.25,-53.85 v2(84.6,-53.5) ; U35.2@82.85,-9.4 82.851,-9.399 82.851,-9.049 83,-8.9 83,-8.36 C206.1@83.06,-8.3 v1(83.9,-8.3) ; C195.1@83,-43.7 v1(83,-43.08) ; C207.2@84.06,-11 v1(84.9,-11) ; R31.1@84.1,43.68 84.2,43.78 v1(84.2,44.4) ; C187.1@84.26,-50.3 v1(85,-50.3) ; C201.1@85.16,-51.8 v1(85.9,-51.8) ; v1(85.2,38.68) C15.1@85.2,39.3 ; U4.6@85.35,50.35 84.85,50.35 v1(84.8,50.4) ; U4.7@85.65,49.85 84.8,49.85 v1(84.8,50.4) ; U4.5@85.65,50.85 84.9,50.85 84.8,50.75 v1(84.8,50.4) ; C199.1@85.7,-53.44 v1(85.7,-52.7) ; v1(85.9,-16.77) U25.3@85.9,-16.15 ; C10.2@86.56,48.4 v1(87.2,48.4) ; v1(86.6,37.98) C14.1@86.6,38.6 ; C188.1@86.66,-47.8 v1(87.4,-47.8) ; C200.1@86.9,-53.44 v1(86.9,-52.7) ; C7.1@87.27,55.3 87.3,55.33 v1(87.3,56.2) ; v1(88.1,38.08) C13.1@88.1,38.7 ; U4.4@88.55,50.85 89.25,50.85 v1(89.3,50.9) ; v1(89.7,27.3) C22.1@89.7,27.945 ; v1(90,-57) 90.15,-56.85 D16.8@90.15,-56.15 ; v1(90,-54.3) 90.15,-54.45 D16.3@90.15,-55.15 ; v1(90.9,26.5) C21.1@90.9,27.33 ; R21.1@91,55.4 v1(91.7,55.4) ; v1(91.4,25.3) C16.2@92,25.3 ; C147.1@92.7,-55.24 v1(92.7,-54.5) ; C16.2@93,25.3 v1(93.6,25.3) ; U3.2@93.8,53 v1(94.6,53) v1@94.64,52.96 ; U5.2@94.29,28.25 94.3,28.24 v1(94.3,27.7) ; v2(95.4,-7.1) C145.1@96.14,-7.1 ; C8.1@95.6,52.96 v1(95.6,53.8) ; v1(95.9,25.5) C12.1@95.9,26.14 ; C3.1@96.26,40.5 v1(96.96,40.5) ; C4.1@96.26,41.6 v1(97,41.6) ; C5.1@96.3,46 v1(97,46) ; v1(96.8,37.9) C2.2@96.8,38.5 ; v1(97.08,-38.9) X4.4@97.7,-38.9 ; v1(97.72,-40.1) C138.2@98.34,-40.1 ; C2.2@97.9,39 v1(98.6,39) ; v1(97.9,40.6) C1.1@97.9,41.3 ; C143.1@98,-43.44 v1(98,-42.82) ; v1(98,37.9) C2.2@98,38.5 ; U1.5@98.24,44.7 98.7,44.7 v1(99.3,45.3) ; v1(98.6,34.8) C157.1@98.6,35.54 ; C140.1@99,-43.44 v1(99,-42.82) ; C137.2@99.16,-35.1 v1(99.78,-35.1) 99.78,-36.32 X4.2@99.6,-36.5 ; v1(99.8,26.8) R159.1@99.8,27.42 ; D22.A@100.2,-46.074 v1(100.2,-45.398) ; v1(100.2,46.4) Q1.S@100.2,47.1 ; v1(100.68,-40.2) R145.1@101.3,-40.2 ; v1(101.3,26.8) R158.1@101.3,27.42 ; v1(101.4,46.6) R14.2@101.4,47.22 ; C142.1@101.5,-43.44 v1(101.5,-42.82) ; v1(101.6,-38.8) C155.1@102.34,-38.8 ; v1(101.72,-41.6) C148.1@102.34,-41.6 ; v1(101.78,-35) R144.2@102.4,-35 ; v1(101.82,-36) C153.1@102.44,-36 ; v1(102.4,39.8) Q6.S@102.4,40.7 ; C141.1@102.5,-43.44 v1(102.5,-42.82) ; v1(102.6,46.6) C6.2@102.6,47.24 ; v1(102.8,26.8) R157.1@102.8,27.42 ; v1(103.3,20.9) J37.10@103.3,22.85 ; D23.A@103.7,-46.074 v1(103.7,-45.398) ; R200.2@104.28,-1.6 v1(104.9,-1.6) ; C144.1@104.74,-32 104.74,-31.341 104.8,-31.281 v1(104.8,-31.2) ; C156.1@105.3,40.2 C156.1@105.34,40.2 v1(106.2,40.2) ; v1(105.7,29.2) 105.725,29.225 U26.10@105.725,30.4 ; R148.1@106.6,-31.92 v1(106.6,-31.3) ; R147.1@107.6,-31.92 v1(107.6,-31.3) ; v1(108.2,-44.18) C149.1@108.2,-43.56 ; C152.1@108.6,-31.9 v1(108.6,-31.3) ; L24.1@108.9,-45.5 v1(108.9,-44.88) ; R146.1@109.6,-31.92 v1(109.6,-31.3) ; L24.1@109.7,-45.5 v1(109.7,-44.88) ; U20.11@110.7,-39.1 v1(111.6,-39.1) ; L25.1@111.3,-45.5 v1(111.3,-44.88) ; L25.1@112.1,-45.5 v1(112.1,-44.88) ; C150.1@113.76,-39.6 v1(114.5,-39.6) ; C154.1@113.82,-37.8 v1(114.5,-37.8) ; C151.1@113.82,-36.8 v1(114.5,-36.8) ; R198.1@114.28,6.1 v1(114.9,6.1) ; v1(115.2,19) R194.1@115.2,19.62 ; v1(117.2,18.5) 118.2,18.5 C185.1@118.2,19.1 117.7,19.6 v1(117.2,19.6) ; R204.2@117.6,41.78 v1(117.6,42.5) ; R96.1@119.38,-41.5 v1(120,-41.5) ; R95.1@119.38,-38.5 v1(120,-38.5) ; v1(120.2,42) 120.2,41.35 Q2.D@120.25,41.3 ; C186.1@120.3,20.6 v1(120.3,21.5) ; R11.2@121.78,35.6 v1(122.5,35.6) ; C83.1@-55.9,-45.34 C82.1@-54.7,-45.34 ; C39.2@56.2,-3.78 C39.2@56.22,-3.78 ; C39.2@56.2,-3.78 C39.2@56.2,-3.76 C39.2@56.22,-3.78
  1-TOP w0.25: J13.B1@-38.45,55.735 v2(-38.45,56.65) ; v2(-38.4,53.12) J13.A12@-38.4,54.035 ; v2(-32.4,53.12) J13.A1@-32.4,54.035 ; J13.B12@-32.35,55.735 v2(-32.35,56.65) ; J63.B12@87.85,-61.235 87.85,-62.139 88.2,-62.489 v2(88.2,-62.5) ; J63.A1@87.9,-59.535 v2(87.9,-58.4) ; v1(93.9,-62.5) 93.9,-62.432 93.95,-62.382 J63.B1@93.95,-61.235 ; J63.A12@93.9,-59.535 v2(93.9,-58.4)
  1-TOP w0.3: v1(-81.275,38.9) J10.3@-81.275,40.375 v1(-81.275,41.85) ; v1(-78.325,38.9) J10.2@-78.325,40.375 v1(-78.325,41.85) ; v1(-78.1,-38.2) -77.4,-38.2 R102.1@-77.3,-38.3 ; v1(-77.52,-37) C63.1@-76.8,-37 ; J31.4@-10.825,-61.2 v2(-10.825,-59.85) ; J31.7@-7.075,-61.2 v2(-7.075,-59.85) ; J31.10@-3.325,-61.2 v2(-3.325,-59.85) ; J31.13@0.425,-61.2 v2(0.425,-59.85) ; U8.2@5.955,43.23 5.955,42.045 6.14,41.86 C29.2@6.14,41.3 6.1,41.26 v1@6.1,40.4 ; v1(13.5,-57.1) R117.2@13.5,-56.48 ; R116.1@13.6,-54 13.7,-54.1 v1(13.7,-54.8) ; U10.2@13.87,43.2 13.87,42.015 14.055,41.83 14.055,41.27 14.015,41.23 14.015,40.315 v1(14,40.3) ; C191.1@16.56,-59.7 v1(17.2,-59.7) ; J19.4@51.8,-10.6 v1(51.8,-9.1) ; v1(53.8,-20.3) J19.9@53.8,-18.8 ; v1(56.2,-20.3) J19.15@56.2,-18.8 ; J19.18@60.6,-10.6 v1(60.6,-9.1) ; v1(61.8,-20.3) J19.21@61.8,-18.8 ; v1(64.2,-20.3) J19.27@64.2,-18.8 ; v1(65,-20.3) J19.29@65,-18.8 ; C110.1@65.36,53.5 v1(66.06,53.5) ; J19.34@67,-10.6 v1(67,-9.1) ; J19.35@67.4,-18.8 v1(67.4,-17.3) ; J19.37@68.2,-18.8 v1(68.2,-17.3) ; J19.40@69.4,-10.6 v1(69.4,-9.1) ; J19.43@70.6,-18.8 v1(70.6,-17.3) ; v2(73.5,56.7) v2(76.9,56.7) C9.2@75.2,56.7 ; v2(73.5,58.2) C9.2@75.2,58.2 v2(76.9,58.2) ; v2(73.5,59.7) v2(76.9,59.7) C9.2@75.2,59.7 ; U30.5@83.9,17.3 v2(84.74,17.3) ; C192.1@86.76,18 v2(87.6,18) ; C193.1@86.76,19.1 v2(87.6,19.1) ; R229.1@86.78,20.2 v2(87.62,20.2) ; v1(92.5,-49.5) C139.2@93.24,-49.5 93.24,-49.04 93.075,-48.875 U19.6@93.075,-47.57 ; C146.2@97.96,-25.3 v2(98.8,-25.3) ; v1(107,-50.1) 107.35,-49.75 U24.3@107.35,-49 ; v1(116.925,-36.85) J24.2@116.925,-35.375 v1(116.925,-33.9) ; v1(119.875,-36.85) J24.3@119.875,-35.375 v1(119.875,-33.9)
  1-TOP w0.4: U11.2@-38.52,43.1 -37.1,43.1 -36,43.1 C28.1@-35.04,43.1 ; C39.2@56.24,-3.8 U12.2@57.82,-3.8 ; J19.26@63.8,-10.6 v2(63.8,-8.2) ; C41.2@72.5,-6.4 v2(72.5,-5.7) ; C41.2@73.1,-7.3 73.1,-7.9 73.4,-8.2 J19.50@73.4,-10.6 ; C20.1@88.7,36 v1(88.7,37) ; C19.1@90.7,36 v1(90.7,37) ; C18.1@92.7,36 v1(92.7,37) ; C17.1@94.7,36 v1(94.7,37) ; C3.1@96.26,40.5 C4.1@96.26,41.6
  1-TOP w0.5: v2(-38.9,-49.2) -37.9,-49.2 R100.1@-37.8,-49.3 ; R100.1@-36.2,-49.2 v2(-35.1,-49.2) ; C190.1@33.2,-56.3 v1(33.2,-55) ; v2(49.9,58.8) J30.15@49.9,60.2 ; v2(52.9,55.125) J30.12@52.9,56.55 ; v2(55.9,58.8) J30.9@55.9,60.2 ; J30.6@58.9,56.55 58.9,55.125 v2(58.925,55.1)
  other v1: 91.9,-63.2 89.9,-63.1 29.6,-58 89.9,-57.8 91.9,-57.8 35.4,-57.7 36.5,-57.7 37.6,-57.7 16.5,-57.5 20.1,-57.4 18.5,-57.3 21.7,-57.3 25.6,-57.3 31.1,-56.9 30.1,-56.2 22.2,-55.9 25.6,-55.7 16.5,-55.6 31.2,-55.4 20.9,-55 28.9,-55 33.2,-54.3 22.2,-54 45.3,-53.8 25.8,-53.7 30.5,-53.7 -21.1,-52.4 22.7,-52.4 -28.5,-51.7 104.9,-50.1 -23,-49.6 18.9,-49 20.5,-49 25.1,-48.8 82.7,-47.8 106.37,-47.64 26.6,-47.2 -72.2,-47 17,-46.6 19,-46.6 21.1,-46.6 23.2,-46.6 32.1,-46.5 33.8,-46.1 35.3,-45.9 -52.6,-45.8 -73.5,-45.6 -71.8,-45.6 37.2,-45.3 105.8,-45.1 107.9,-44.9 -65.8,-44.7 -51.4,-44.7 24.4,-44.3 26,-44.3 108.98,-44.1 -65.1,-43.5 37.1,-43 38.654,-43 -47.4,-42.9 110.7,-42.9 111.8,-42.9 117.3,-42.7 119.5,-42.7 -45.4,-42.4 25.9,-42.2 27.3,-42.2 117.3,-41.1 111.8,-40.6 119.5,-40.6 117.3,-39.7 37.1,-39.4 38.5,-39.4 119.5,-39.4 117.3,-38.1 -71.8,-36.9 -70.7,-36.9 -69.5,-36.9 -68.4,-36.9 -52.85,-36.9 -51.75,-36.9 -50.55,-36.9 -49.45,-36.9 47.595,-36.805 49.7,-36.805 51.805,-36.805 -71.8,-35.8 -70.7,-35.8 -69.5,-35.8 -68.4,-35.8 -52.85,-35.8 -50.55,-35.8 -49.45,-35.8 47.595,-34.7 51.805,-34.7 -71.8,-34.6 -70.7,-34.6 -69.5,-34.6 -68.4,-34.6 -52.85,-34.6 -51.75,-34.6 -50.55,-34.6 -49.45,-34.6 118.4,-34 -71.8,-33.5 -70.7,-33.5 -69.5,-33.5 -68.4,-33.5 -52.85,-33.5 -51.75,-33.5 -50.55,-33.5 -49.45,-33.5 100.1,-33.3 101.7,-33.3 47.595,-32.595 49.7,-32.595 51.805,-32.595 -67.3,-27.3 88.459,-26.8 90.359,-26.8 13.4,-26.2 14.2,-26.2 11.9,-26.1 18.7,-26 15.5,-25.9 17.1,-24.8 -69.8,-24.7 -68.2,-24.3 15.8,-23.2 -70.9,-23 14.6,-21.5 -74.1,-20.2 -38.2,-19.9 -72.4,-19.8 89.4,-18.3 83.4,-17.7 85.2,-17.7 91.4,-17.4 -38.7,-16.5 -40.7,-15.6 87.3,-15.2 -37.2,-15.1 -40,-14.6 -36.6,-14.6 -42.1,-14.5 -55.8,-13.9 -65.661,-13.827 -71.2,-13.8 -68.2,-13.8 -61.2,-13.8 -58.3,-13.8 -42.4,-12.5 -21.1,-11.7 -70.2,-10.5 -68,-10.3 -61.2,-10 -58.3,-10 -20.95,-9.575 -22.1,-9.1 -68.2,-8.1 -55.8,-8.1 -21.6,-7.2 -68,-4.5 -61.3,-4.4 -58.3,-4.2 -68.2,-2.2 -55.8,-2.2 -71,-2.1 -65.7,1.5 -58.3,3.3 -68.2,3.4 -61.2,3.4 -55.7,3.4 -70.7,3.9 -68.2,7.1 -65.8,7.2 -58.2,7.2 -55.8,7.3 -70.5,9.8 -65.7,13.3 -61.2,14.9 -58.3,14.9 -55.8,15 -68.2,15.1 -70.5,15.5 95.1,28.5 -53.8,29.8 -54.2,32.3 -52.4,32.3 89.7,37 91.7,37 93.7,37 88.7,37.7 89.7,37.7 90.7,37.7 91.7,37.7 92.7,37.7 81.2,38.5 -79.8,39 6.1,40.3 -80.9,43.1 -78.7,44.3 -80.9,44.7 -78.7,45.5 -80.9,46.1 -80.9,47.7 -78.7,47.7 -41.8,50.05 -41,50.05 -40.2,50.05 -41.8,50.85 -41,50.85 -40.2,50.85 -41.8,51.65 -41,51.65 -40.2,51.65 -36.4,52.1 -34.5,52.1 54.8,53.9 50.9,54 56.8,54.1 -34.4,57.6 -36.4,57.7
  other v2: 44.36,-64.98 47.36,-64.98 50.36,-64.98 53.36,-64.98 101.36,-64.98 104.36,-64.98 107.36,-64.98 110.36,-64.98 113.36,-64.98 -80.14,-61.98 -59.14,-61.98 -35.14,-61.98 -23.14,-61.98 -20.14,-61.98 -17.14,-61.98 12.86,-61.98 60.86,-61.98 63.86,-61.98 66.86,-61.98 75.86,-61.98 78.86,-61.98 81.86,-61.98 102.86,-61.98 105.86,-61.98 108.86,-61.98 111.86,-61.98 117.86,-61.98 -84.64,-58.98 -36.64,-58.98 -15.64,-58.98 -6.64,-58.98 -3.64,-58.98 5.36,-58.98 14.36,-58.98 44.36,-58.98 47.36,-58.98 50.36,-58.98 53.36,-58.98 62.36,-58.98 74.36,-58.98 77.36,-58.98 80.36,-58.98 83.36,-58.98 104.36,-58.98 107.36,-58.98 116.36,-58.98 119.36,-58.98 -35.14,-55.98 -32.14,-55.98 -20.14,-55.98 -11.14,-55.98 60.86,-55.98 63.86,-55.98 75.86,-55.98 93.86,-55.98 117.86,-55.98 120.86,-55.98 -84.64,-52.98 -6.64,-52.98 -0.64,-52.98 2.36,-52.98 5.36,-52.98 8.36,-52.98 41.36,-52.98 56.36,-52.98 59.36,-52.98 62.36,-52.98 65.36,-52.98 68.36,-52.98 74.36,-52.98 77.36,-52.98 92.36,-52.98 95.36,-52.98 116.36,-52.98 119.36,-52.98 -62.14,-49.98 -41.14,-49.98 -32.14,-49.98 -29.14,-49.98 -14.14,-49.98 -2.14,-49.98 9.86,-49.98 54.86,-49.98 57.86,-49.98 60.86,-49.98 63.86,-49.98 75.86,-49.98 117.86,-49.98 -84.64,-46.98 -0.64,-46.98 5.36,-46.98 8.36,-46.98 11.36,-46.98 29.36,-46.98 35.36,-46.98 41.36,-46.98 62.36,-46.98 65.36,-46.98 113.36,-46.98 -83.14,-43.98 -23.14,-43.98 -8.14,-43.98 15.86,-43.98 27.86,-43.98 84.86,-43.98 87.86,-43.98 90.86,-43.98 99.86,-43.98 111.86,-43.98 -39.64,-40.98 5.36,-40.98 14.36,-40.98 17.36,-40.98 59.36,-40.98 74.36,-40.98 77.36,-40.98 80.36,-40.98 83.36,-40.98 86.36,-40.98 98.36,-40.98 116.36,-40.98 106.9,-38.6 108.9,-38.6 -38.14,-37.98 -35.14,-37.98 -32.14,-37.98 57.86,-37.98 60.86,-37.98 63.86,-37.98 72.86,-37.98 75.86,-37.98 81.86,-37.98 84.86,-37.98 87.86,-37.98 90.86,-37.98 120.86,-37.98 106.9,-36.5 108.9,-36.5 -39.64,-34.98 -36.64,-34.98 -33.64,-34.98 -30.64,-34.98 17.36,-34.98 32.36,-34.98 62.36,-34.98 68.36,-34.98 74.36,-34.98 77.36,-34.98 80.36,-34.98 83.36,-34.98 86.36,-34.98 92.36,-34.98 95.36,-34.98 -41.14,-31.98 -38.14,-31.98 -35.14,-31.98 -29.14,-31.98 -26.14,-31.98 -23.14,-31.98 -8.14,-31.98 -2.14,-31.98 0.86,-31.98 84.86,-31.98 87.86,-31.98 90.86,-31.98 117.86,-31.98 120.86,-31.98 107.36,-28.98 119.36,-28.98 -74.14,-25.98 39.86,-25.98 54.86,-25.98 60.86,-25.98 66.86,-25.98 69.86,-25.98 72.86,-25.98 75.86,-25.98 81.86,-25.98 93.86,-25.98 99.86,-25.98 102.86,-25.98 105.86,-25.98 108.86,-25.98 111.86,-25.98 117.86,-25.98 120.86,-25.98 62.36,-22.98 65.36,-22.98 74.36,-22.98 77.36,-22.98 80.36,-22.98 89.36,-22.98 92.36,-22.98 95.36,-22.98 98.36,-22.98 104.36,-22.98 107.36,-22.98 116.36,-22.98 119.36,-22.98 -62.14,-19.98 6.86,-19.98 87.86,-19.98 114.86,-19.98 117.86,-19.98 120.86,-19.98 35.36,-16.98 38.36,-16.98 41.36,-16.98 44.36,-16.98 62.36,-16.98 65.36,-16.98 71.36,-16.98 74.36,-16.98 80.36,-16.98 95.36,-16.98 98.36,-16.98 104.36,-16.98 107.36,-16.98 113.36,-16.98 116.36,-16.98 119.36,-16.98 -62.14,-13.98 -29.14,-13.98 -26.14,-13.98 39.86,-13.98 42.86,-13.98 45.86,-13.98 51.86,-13.98 60.86,-13.98 63.86,-13.98 66.86,-13.98 72.86,-13.98 75.86,-13.98 81.86,-13.98 93.86,-13.98 99.86,-13.98 102.86,-13.98 105.86,-13.98 108.86,-13.98 114.86,-13.98 117.86,-13.98 120.86,-13.98 86.36,-10.98 92.36,-10.98 104.36,-10.98 107.36,-10.98 113.36,-10.98 116.36,-10.98 119.36,-10.98 42.86,-7.98 45.86,-7.98 84.86,-7.98 93.86,-7.98 96.86,-7.98 99.86,-7.98 114.86,-7.98 117.86,-7.98 120.86,-7.98 38.36,-4.98 41.36,-4.98 47.36,-4.98 50.36,-4.98 53.36,-4.98 74.36,-4.98 77.36,-4.98 80.36,-4.98 83.36,-4.98 86.36,-4.98 116.36,-4.98 119.36,-4.98 -77.14,-1.98 36.86,-1.98 42.86,-1.98 48.86,-1.98 51.86,-1.98 54.86,-1.98 57.86,-1.98 72.86,-1.98 75.86,-1.98 81.86,-1.98 84.86,-1.98 87.86,-1.98 96.86,-1.98 117.86,-1.98 120.86,-1.98 32.36,1.02 35.36,1.02 38.36,1.02 98.36,1.02 101.36,1.02 104.36,1.02 110.36,1.02 113.36,1.02 116.36,1.02 48.86,4.02 51.86,4.02 54.86,4.02 57.86,4.02 60.86,4.02 72.86,4.02 75.86,4.02 81.86,4.02 84.86,4.02 87.86,4.02 93.86,4.02 96.86,4.02 102.86,4.02 111.86,4.02 114.86,4.02 -84.64,7.02 35.36,7.02 38.36,7.02 41.36,7.02 44.36,7.02 47.36,7.02 53.36,7.02 56.36,7.02 59.36,7.02 62.36,7.02 71.36,7.02 77.36,7.02 80.36,7.02 83.36,7.02 86.36,7.02 95.36,7.02 101.36,7.02 104.36,7.02 107.36,7.02 116.36,7.02 119.36,7.02 -83.14,10.02 39.86,10.02 42.86,10.02 54.86,10.02 57.86,10.02 60.86,10.02 81.86,10.02 84.86,10.02 87.86,10.02 90.86,10.02 96.86,10.02 102.86,10.02 111.86,10.02 114.86,10.02 117.86,10.02 120.86,10.02 -84.64,13.02 32.36,13.02 44.36,13.02 47.36,13.02 50.36,13.02 53.36,13.02 56.36,13.02 59.36,13.02 62.36,13.02 71.36,13.02 74.36,13.02 101.36,13.02 104.36,13.02 107.36,13.02 110.36,13.02 113.36,13.02 116.36,13.02 119.36,13.02 48.86,16.02 51.86,16.02 54.86,16.02 57.86,16.02 60.86,16.02 81.86,16.02 84.86,16.02 90.86,16.02 93.86,16.02 96.86,16.02 -78.64,19.02 77.36,19.02 89.36,19.02 95.36,19.02 110.36,19.02 116.36,19.02 119.36,19.02 -17.14,22.02 54.86,22.02 57.86,22.02 60.86,22.02 -42.64,25.02 -39.64,25.02 56.36,25.02 71.36,25.02 116.36,25.02 -77.14,28.02 -41.14,28.02 39.86,28.02 48.86,28.02 51.86,28.02 75.86,28.02 78.86,28.02 81.86,28.02 105.86,28.02 108.86,28.02 111.86,28.02 114.86,28.02 120.86,28.02 -65.6,30.4 -63.6,30.4 -61.6,30.4 -78.64,31.02 -75.64,31.02 -72.64,31.02 38.36,31.02 53.36,31.02 77.36,31.02 80.36,31.02 113.36,31.02 116.36,31.02 -65.6,32.4 -61.6,32.4 -74.14,34.02 45.86,34.02 54.86,34.02 60.86,34.02 69.86,34.02 78.86,34.02 96.86,34.02 102.86,34.02 111.86,34.02 120.86,34.02 -65.6,34.4 -63.6,34.4 -61.6,34.4 -84.64,37.02 -81.64,37.02 -78.64,37.02 -72.64,37.02 -54.64,37.02 -51.64,37.02 -48.64,37.02 -42.64,37.02 -39.64,37.02 -36.64,37.02 -33.64,37.02 -30.64,37.02 -27.64,37.02 38.36,37.02 68.36,37.02 71.36,37.02 113.36,37.02 -83.14,40.02 -80.14,40.02 -77.14,40.02 -74.14,40.02 -53.14,40.02 -50.14,40.02 -41.14,40.02 -38.14,40.02 -35.14,40.02 -32.14,40.02 -29.14,40.02 -8.14,40.02 72.86,40.02 111.86,40.02 114.86,40.02 117.86,40.02 107.7,43 -84.64,43.02 -81.64,43.02 -75.64,43.02 -72.64,43.02 -57.64,43.02 -54.64,43.02 11.36,43.02 17.36,43.02 44.36,43.02 56.36,43.02 59.36,43.02 65.36,43.02 71.36,43.02 74.36,43.02 77.36,43.02 96.8,43.2 107.7,43.9 96.8,44.3 107.7,44.8 -83.14,46.02 -77.14,46.02 -74.14,46.02 -71.14,46.02 -65.14,46.02 -62.14,46.02 -56.14,46.02 -53.14,46.02 -47.14,46.02 0.86,46.02 3.86,46.02 6.86,46.02 9.86,46.02 12.86,46.02 15.86,46.02 18.86,46.02 24.86,46.02 117.86,46.02 120.86,46.02 -84.64,49.02 -72.64,49.02 -63.64,49.02 -60.64,49.02 -54.64,49.02 -51.64,49.02 -30.64,49.02 -18.64,49.02 -9.64,49.02 -6.64,49.02 59.36,49.02 62.36,49.02 68.36,49.02 71.36,49.02 92.36,49.02 101.36,49.02 104.36,49.02 116.36,49.02 87.1,50.1 -83.14,52.02 -77.14,52.02 -74.14,52.02 -71.14,52.02 -68.14,52.02 -65.14,52.02 -62.14,52.02 -59.14,52.02 -53.14,52.02 -47.14,52.02 -26.14,52.02 -17.14,52.02 -14.14,52.02 -11.14,52.02 -8.14,52.02 -5.14,52.02 15.86,52.02 18.86,52.02 24.86,52.02 51.86,52.02 60.86,52.02 69.86,52.02 72.86,52.02 75.86,52.02 78.86,52.02 84.86,52.02 96.86,52.02 99.86,52.02 102.86,52.02 -84.64,55.02 -75.64,55.02 -72.64,55.02 -69.64,55.02 -63.64,55.02 -60.64,55.02 -54.64,55.02 -51.64,55.02 -15.64,55.02 -12.64,55.02 -3.64,55.02 8.36,55.02 20.36,55.02 26.36,55.02 41.36,55.02 65.36,55.02 68.36,55.02 71.36,55.02 74.36,55.02 77.36,55.02 80.36,55.02 92.36,55.02 95.36,55.02 98.36,55.02 116.36,55.02 -77.14,58.02 -74.14,58.02 -71.14,58.02 -65.14,58.02 -62.14,58.02 -56.14,58.02 -53.14,58.02 -38.14,58.02 -32.14,58.02 -29.14,58.02 -14.14,58.02 -11.14,58.02 -8.14,58.02 -5.14,58.02 -2.14,58.02 0.86,58.02 3.86,58.02 6.86,58.02 9.86,58.02 12.86,58.02 15.86,58.02 45.86,58.02 48.86,58.02 60.86,58.02 66.86,58.02 69.86,58.02 78.86,58.02 81.86,58.02 84.86,58.02 87.86,58.02 96.86,58.02
GPIO3_IO26_1V8: J65.3 R244.2 U7.AL18 | length 219.2
  1-TOP w0.2: U7.AL18@17.78,3.81 v1(18.415,4.445) ; v1(41.5,-45.2) 41.5,-45.6 42,-46.1 42,-46.9 42.852,-47.752 43.272,-47.752 R244.2@43.32,-47.8
  3-INTOP w0.2: J65.3@-81.2,-7.86 -79.76,-7.86 -71.2,0.7 -48.5,0.7 -48.1,1.1 -45.8,1.1 -44.8,0.1 -37.241,0.1 -36.741,0.6 v1(-32.5,0.6) ; v1(-31.7,-17) -24.3,-17 -20.4,-20.9 9.6,-20.9 10.3,-21.6 12.2,-21.6 13.9,-19.9 13.9,-1.6 14.3,-1.2 17,-1.2 17.8,-0.4 17.8,3.83 v1(18.415,4.445)
  6-INBOT w0.2: v1(-32.5,0.6) -31.7,-0.2 v1@-31.7,-16.984 ; v1(18.415,4.445) 25.655,4.445 30.4,-0.3 v1(30.4,-36.7)
  8-BOTTOM w0.2: v1(30.4,-36.7) 37.7,-36.7 39.7,-38.7 39.7,-40.5 41.5,-42.3 v1(41.5,-45.2)
GPIO3_IO27_1V8: J65.5 U7.D25 | length 98.1
  1-TOP w0.15: J65.5@-81.2,-10.4 -78.4,-10.4 -77.7,-9.7 v1(-73.5,-9.7)
  1-TOP w0.2: U7.D25@-16.51,12.7 v1(-15.875,13.335)
  3-INTOP w0.2: v1(-74.3,15.6) -71.646,18.254 -48.254,18.254 -41.4,11.4 -17.1,11.4 -16.5,12 -16.5,12.71 v1(-15.875,13.335)
  6-INBOT w0.2: v1(-74.3,15.6) -74.3,9.1 -73.5,8.3 v1(-73.5,-9.7)
GPIO4_IO16_1V8: J52.3 J65.7 | length 18.7
  1-TOP w0.2: J65.7@-81.2,-12.94 -79.94,-14.2 -72.609,-14.2 -70.509,-16.3 -66.02,-16.3 J52.3@-64.52,-14.8
GPIO4_IO17_1V8: J45.3 J65.9 | length 29.9
  1-TOP w0.2: J65.9@-81.2,-15.48 -81.18,-15.5 v1(-72.9,-15.5)
  6-INBOT w0.2: v1(-72.9,-15.5) -72.9,-14.5 -71.2,-12.8 -58.42,-12.8 J45.3@-54.62,-9
GPIO4_IO22_1V8: J55.3 J65.4 | length 36.2
  1-TOP w0.2: J65.4@-83.74,-7.86 -82.48,-6.6 -75.6,-6.6 v1(-73,-4)
  6-INBOT w0.2: v1(-73,-4) -73,8.2 -69.3,11.9 -65.5,11.9 -64.52,12.88 J55.3@-64.52,14.1
GPIO4_IO25_1V8: J56.3 J65.6 | length 36
  1-TOP w0.2: J65.6@-83.74,-10.4 -82.44,-9.1 v1(-72.5,-9.1)
  6-INBOT w0.2: v1(-72.5,-9.1) -72.5,5 -71.6,5.9 -65.6,5.9 -64.52,6.98 J56.3@-64.52,8.3
GPIO4_IO27_1V8: J60.3 J65.8 | length 40.8
  1-TOP w0.2: J65.8@-83.74,-12.94 -82.5,-11.7 v1(-65.8,-11.7)
  6-INBOT w0.2: v1(-65.8,-11.7) -65.8,-2.6 -62.1,1.1 -56.02,1.1 J60.3@-54.62,2.5
HDMI_CLK_N: L21.1 U17.21 | length 5
  1-TOP w0.15: L21.1@47.925,-43.15 48.025,-43.05 48.025,-42.328 48.175,-42.178 48.175,-40.875 48.028,-40.728 48.028,-39.577 48.323,-39.282 48.323,-38.428 U17.21@48.3,-38.405
HDMI_CLK_P: L21.4 U17.22 | length 5
  1-TOP w0.15: 48.377,-39.724 48.377,-40.556 48.525,-40.704 48.525,-42.325 48.377,-42.473 48.377,-43.052 L21.4@48.475,-43.15 ; 48.382,-39.724 48.677,-39.429 48.677,-38.428 U17.22@48.7,-38.405
HDMI_D0_N: L20.1 U17.24 | length 5
  1-TOP w0.15: L20.1@49.425,-43.15 49.523,-43.052 49.523,-41.82 49.225,-41.522 49.225,-40.375 49.523,-40.077 U17.24@49.523,-38.433 ; U17.24@49.5,-38.405 U17.24@49.528,-38.433
HDMI_D0_P: L20.4 U17.25 | length 5
  1-TOP w0.15: U17.25@49.877,-38.433 49.877,-40.198 49.575,-40.5 49.575,-41.371 49.877,-41.673 49.877,-43.052 L20.4@49.975,-43.15 ; U17.25@49.882,-38.423 U17.25@49.9,-38.405
HDMI_D1_N: L19.1 U17.27 | length 5
  1-TOP w0.15: U17.27@50.7,-38.405 50.723,-38.428 50.723,-39.318 51.023,-39.618 51.023,-40.476 51.175,-40.628 51.173,-40.63 51.173,-41.527 51.023,-41.677 51.023,-43.052 L19.1@50.925,-43.15
HDMI_D1_P: L19.4 U17.28 | length 5
  1-TOP w0.15: U17.28@51.1,-38.405 51.077,-38.428 51.077,-39.171 51.377,-39.471 51.377,-40.367 51.527,-40.517 51.527,-41.674 51.377,-41.824 51.377,-43.052 L19.4@51.475,-43.15
HDMI_D2_N: L18.1 U17.30 | length 5
  1-TOP w0.15: U17.30@51.9,-38.405 51.923,-38.428 51.923,-38.619 51.923,-39.419 52.523,-40.019 52.523,-43.052 L18.1@52.425,-43.15
HDMI_D2_P: L18.4 U17.31 | length 5
  1-TOP w0.15: U17.31@52.3,-38.405 52.277,-38.428 52.277,-39.272 52.877,-39.872 52.877,-43.052 L18.4@52.975,-43.15
HDMI_FIL_CLK_N: J32.12 L21.2 U18.15 U18.24 | length 11.8
  1-TOP w0.15: J32.12@47.7,-56.3 U18.15@47.7,-46.5 47.7,-45.2 47.925,-44.975 L21.2@47.925,-44.55
HDMI_FIL_CLK_P: J32.10 L21.3 U18.13 U18.26 | length 11.9
  1-TOP w0.15: L21.3@48.475,-44.45 48.475,-44.975 48.7,-45.2 U18.13@48.7,-46.5 J32.10@48.7,-56.3
HDMI_FIL_D0_N: J32.9 L20.2 U18.12 U18.27 | length 11.9
  1-TOP w0.15: J32.9@49.2,-56.3 U18.12@49.2,-46.5 49.2,-45.2 49.425,-44.975 L20.2@49.425,-44.45
HDMI_FIL_D0_P: J32.7 L20.3 U18.10 U18.29 | length 11.9
  1-TOP w0.15: L20.3@49.975,-44.45 49.975,-44.975 50.2,-45.2 U18.10@50.2,-46.5 J32.7@50.2,-56.3
HDMI_FIL_D1_N: J32.6 L19.2 U18.9 U18.30 | length 11.9
  1-TOP w0.15: J32.6@50.7,-56.3 U18.9@50.7,-46.5 50.7,-45.2 50.925,-44.975 L19.2@50.925,-44.45
HDMI_FIL_D1_P: J32.4 L19.3 U18.7 U18.32 | length 11.9
  1-TOP w0.15: L19.3@51.475,-44.45 51.475,-44.975 51.7,-45.2 U18.7@51.7,-46.5 U18.32@51.7,-52.3 J32.4@51.7,-56.3
HDMI_FIL_D2_N: J32.3 L18.2 U18.6 U18.33 | length 11.9
  1-TOP w0.15: J32.3@52.2,-56.3 U18.33@52.2,-52.3 U18.6@52.2,-46.5 52.2,-45.2 52.425,-44.975 L18.2@52.425,-44.45
HDMI_FIL_D2_P: J32.1 L18.3 U18.4 U18.35 | length 11.9
  1-TOP w0.15: L18.3@52.975,-44.45 52.975,-44.975 53.2,-45.2 U18.4@53.2,-46.5 J32.1@53.2,-56.3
